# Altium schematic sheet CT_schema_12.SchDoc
size 519 x 434 mm
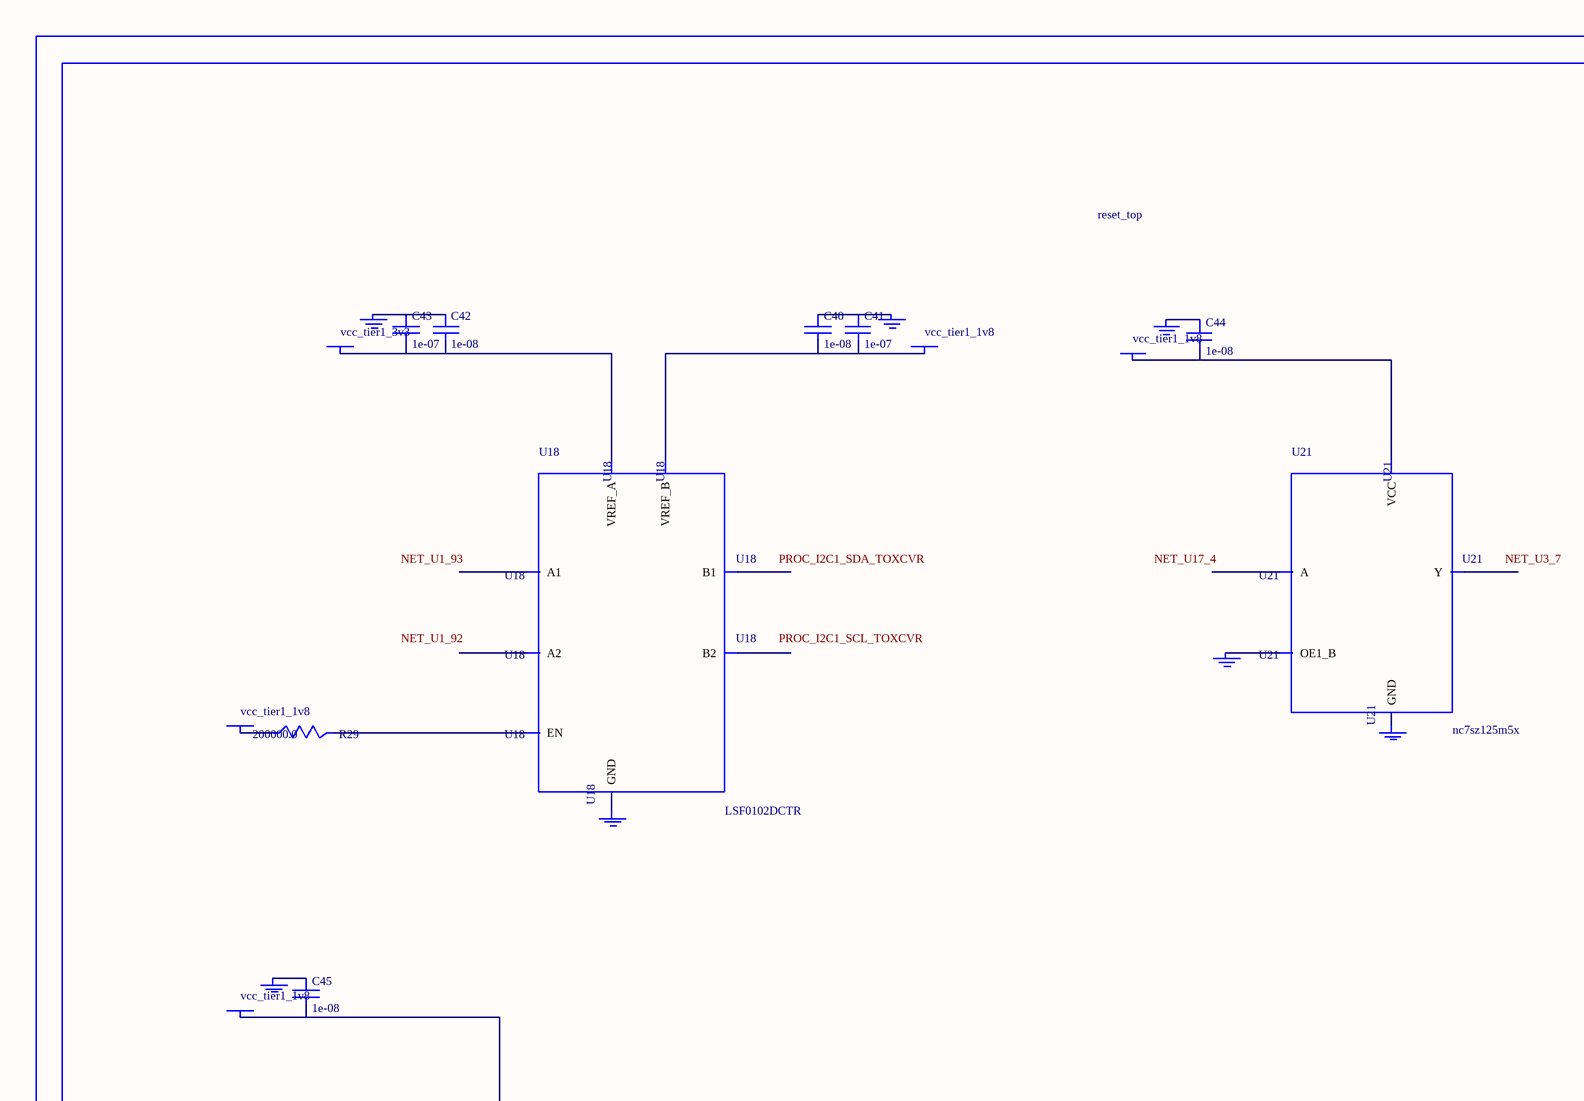
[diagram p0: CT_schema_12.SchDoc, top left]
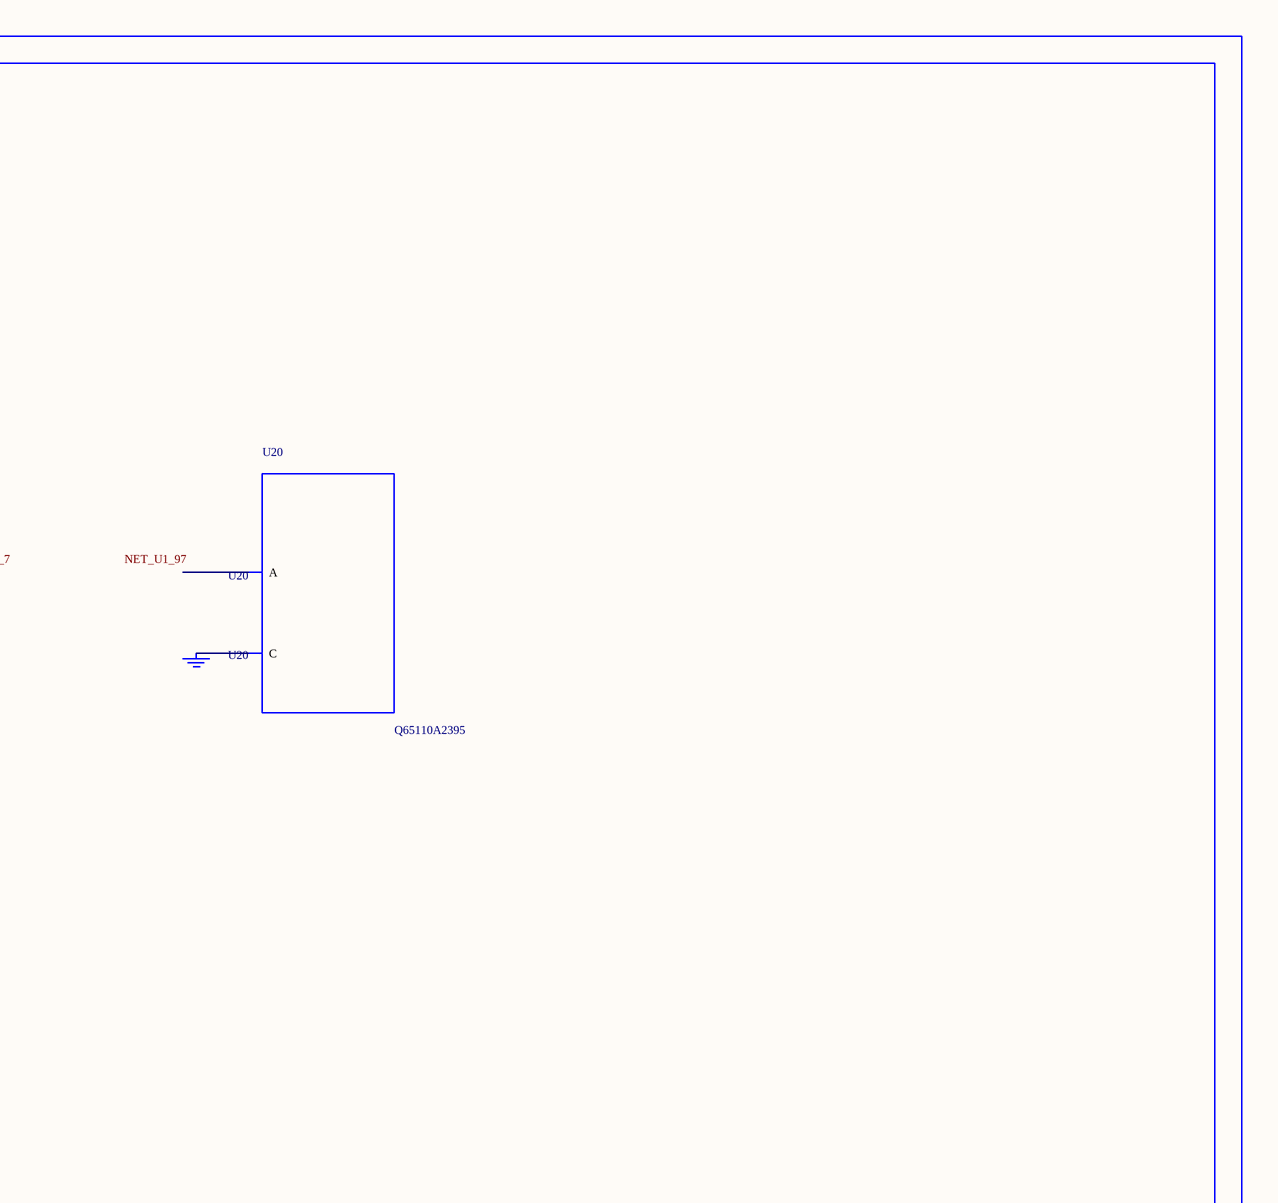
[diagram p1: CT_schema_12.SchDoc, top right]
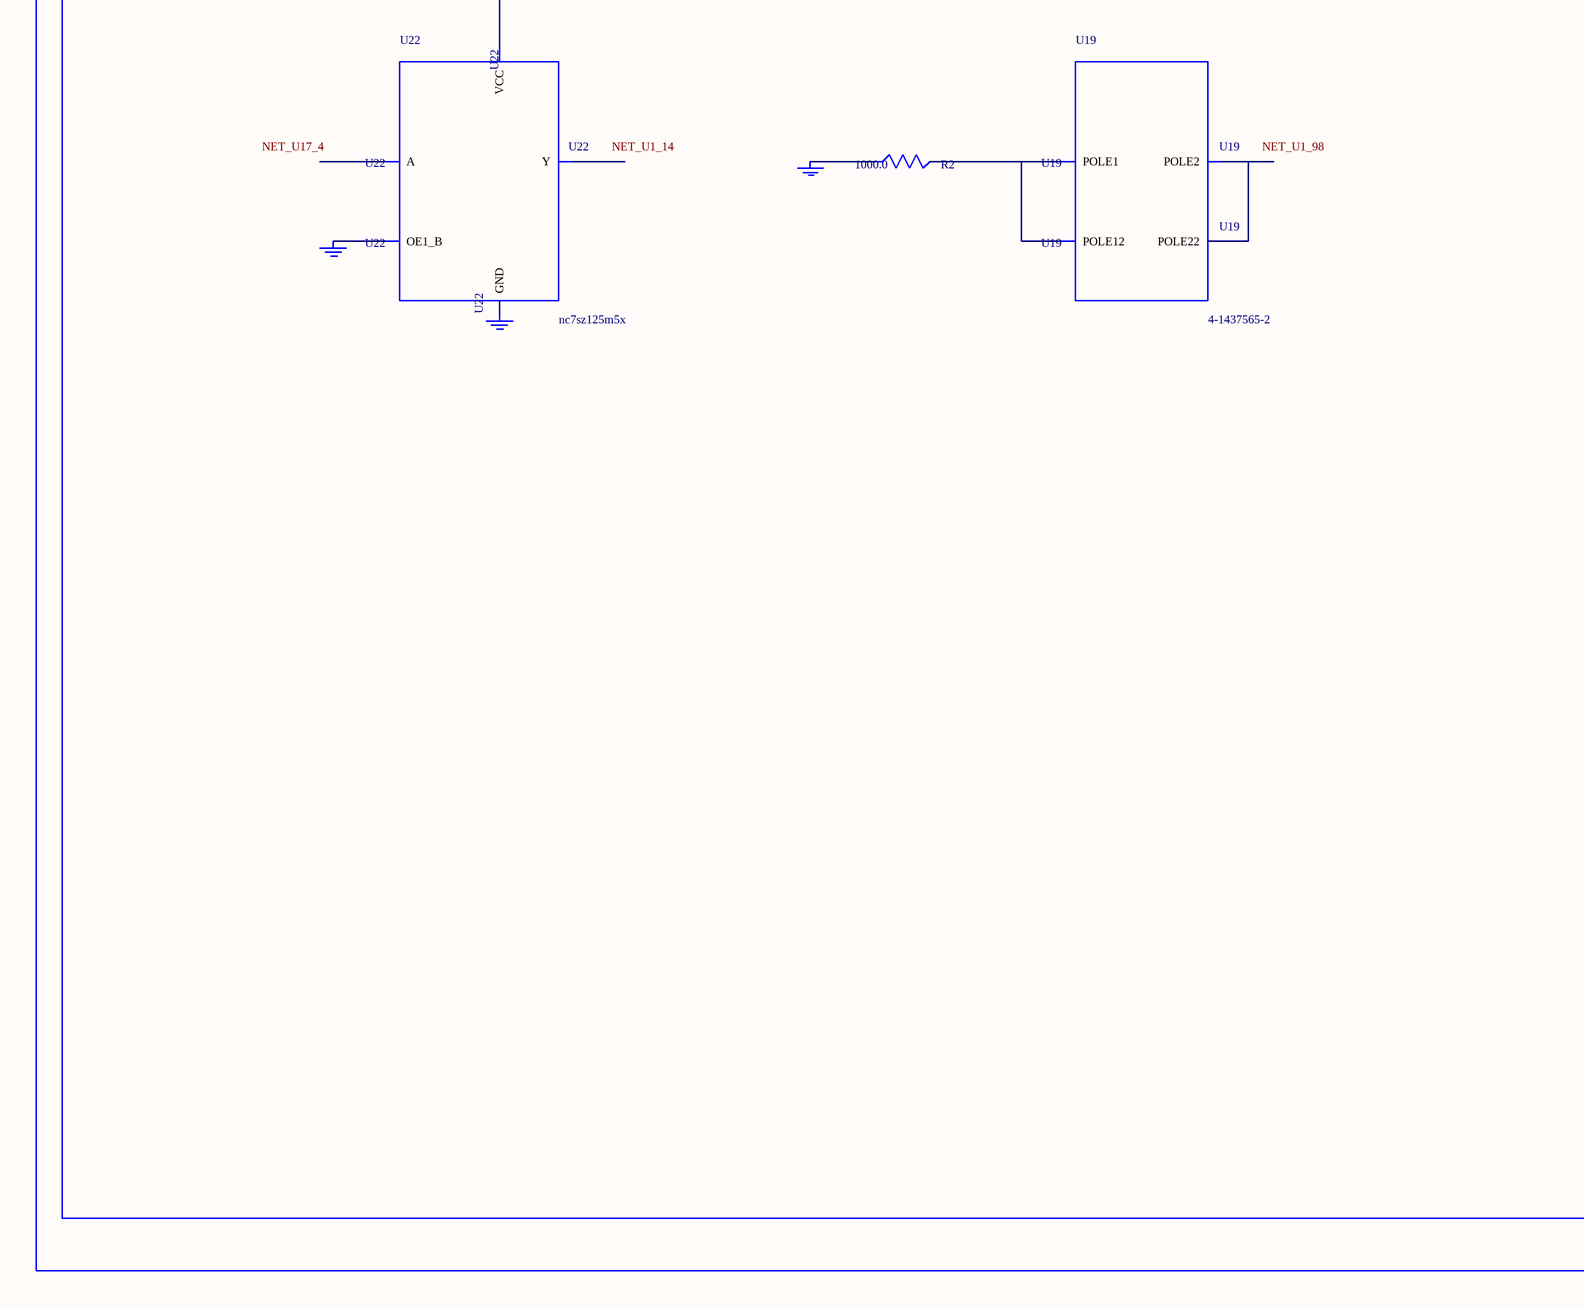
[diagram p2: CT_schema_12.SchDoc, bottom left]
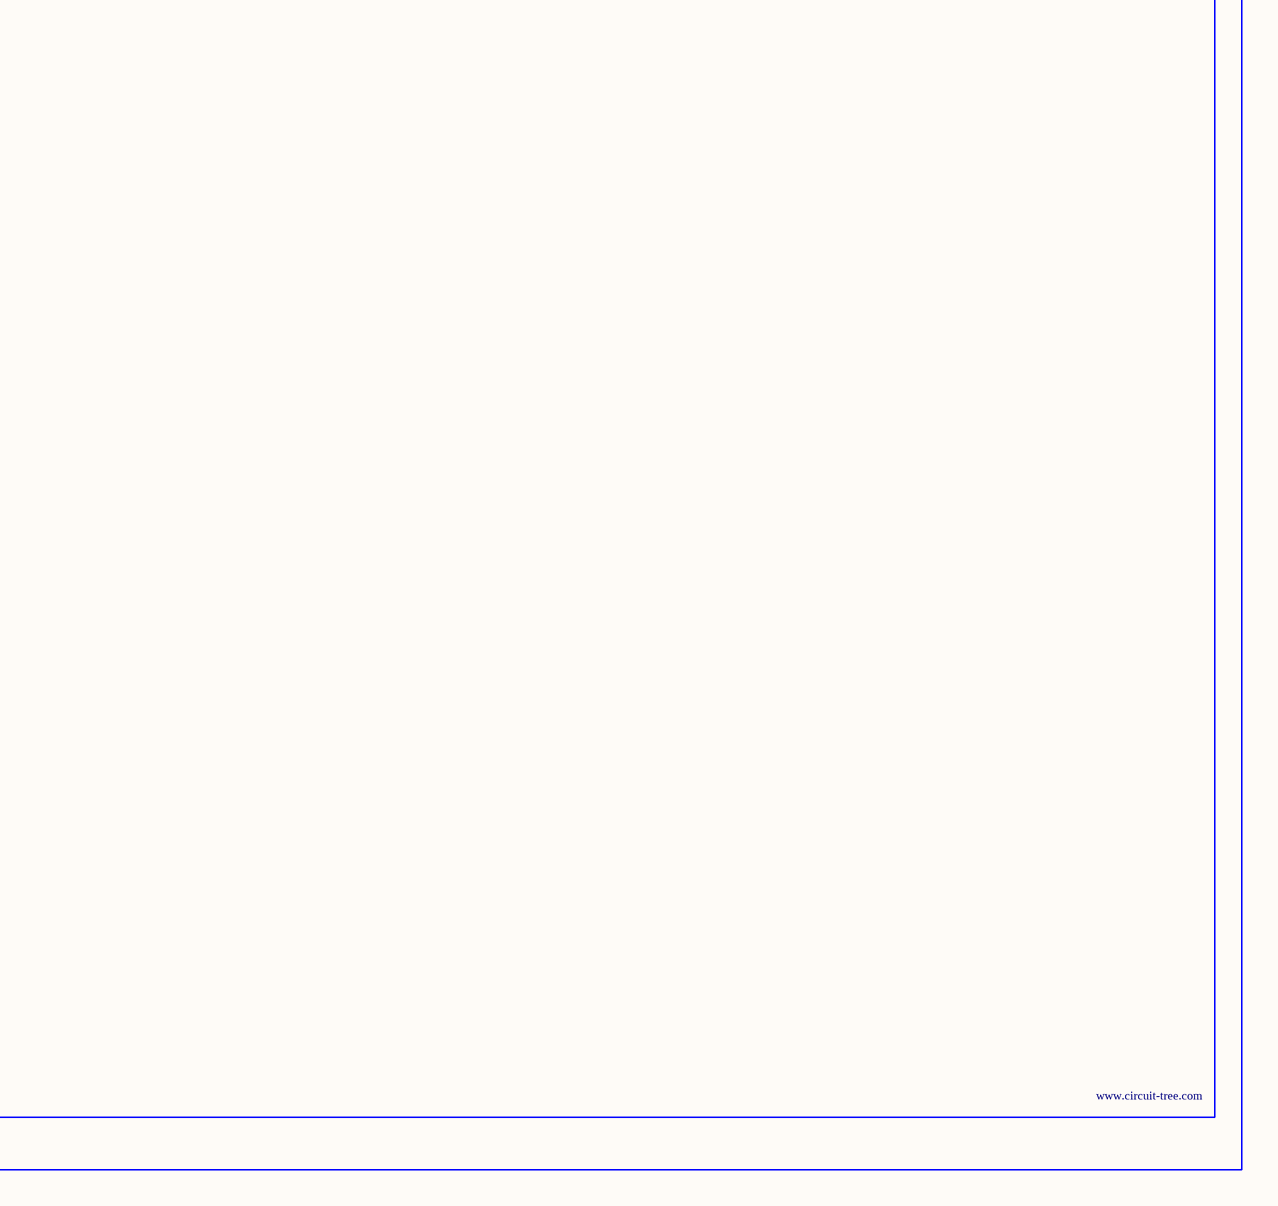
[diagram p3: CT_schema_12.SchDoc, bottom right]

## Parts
BORDER11  (no value)
C40  1e-08  [C0402]
C41  1e-07  [C0402]
C42  1e-08  [C0402]
C43  1e-07  [C0402]
C44  1e-08  [C0402]
C45  1e-08  [C0402]
GND_INSTANCE_11_0  (no value)
GND_INSTANCE_11_1  (no value)
GND_INSTANCE_11_2  (no value)
GND_INSTANCE_11_3  (no value)
GND_INSTANCE_11_4  (no value)
GND_INSTANCE_11_5  (no value)
GND_INSTANCE_11_6  (no value)
GND_INSTANCE_11_7  (no value)
GND_INSTANCE_11_8  (no value)
GND_INSTANCE_11_9  (no value)
GND_INSTANCE_11_10  (no value)
POWER_INSTANCE_11_0  vcc_tier1_3v3
POWER_INSTANCE_11_1  vcc_tier1_1v8
POWER_INSTANCE_11_2  vcc_tier1_1v8
POWER_INSTANCE_11_3  vcc_tier1_1v8
POWER_INSTANCE_11_4  vcc_tier1_1v8
R2  1000.0  [R0603]
R29  200000.0  [R0603]
U18  LSF0102DCTR  [DCU0008A_N]
U19  4-1437565-2  [SW_4-1437565-2]
U20  Q65110A2395  [LGM67K-G1J2-24-Z]
U21  nc7sz125m5x  [NC7SZ125M5X]
U22  nc7sz125m5x  [NC7SZ125M5X]

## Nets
NetC40_1: C40.1 C41.1 GND_INSTANCE_11_1.0(GND)
NetC40_2: C40.2 C41.2 POWER_INSTANCE_11_1.0(PWR) U18.7(VREF_B)
NetC42_1: C42.1 C43.1 GND_INSTANCE_11_0.0(GND)
NetC42_2: C42.2 C43.2 POWER_INSTANCE_11_0.0(PWR) U18.2(VREF_A)
NetC44_1: C44.1 GND_INSTANCE_11_5.0(GND)
NetC44_2: C44.2 POWER_INSTANCE_11_3.0(PWR) U21.5(VCC)
NetC45_1: C45.1 GND_INSTANCE_11_8.0(GND)
NetC45_2: C45.2 POWER_INSTANCE_11_4.0(PWR) U22.5(VCC)
NetGND_INSTANCE_11_2_0: GND_INSTANCE_11_2.0(GND) U18.1(GND)
NetGND_INSTANCE_11_3_0: GND_INSTANCE_11_3.0(GND) R2.1
NetGND_INSTANCE_11_4_0: GND_INSTANCE_11_4.0(GND) U20.C
NetGND_INSTANCE_11_6_0: GND_INSTANCE_11_6.0(GND) U21.1(OE1_B)
NetGND_INSTANCE_11_7_0: GND_INSTANCE_11_7.0(GND) U21.3(GND)
NetGND_INSTANCE_11_9_0: GND_INSTANCE_11_9.0(GND) U22.1(OE1_B)
NetGND_INSTANCE_11_10_0: GND_INSTANCE_11_10.0(GND) U22.3(GND)
NetPOWER_INSTANCE_11_2_0: POWER_INSTANCE_11_2.0(PWR) R29.1
NetR2_2: R2.2 U19.1(POLE1) U19.2(POLE12)
NetR29_2: R29.2 U18.8(EN)
NetU19_3: U19.3(POLE2) U19.4(POLE22)

Not connected (* = marked no-connect by the designer): U18 3(A1) 4(A2) 5(B2) 6(B1); U20 A; U21 2(A) 4(Y); U22 2(A) 4(Y)

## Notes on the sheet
- Labels drawn without touching a wire or pin: NET_U1_14, NET_U1_92, NET_U1_93, NET_U1_97, NET_U1_98, NET_U3_7, NET_U17_4, PROC_I2C1_SCL_TOXCVR, PROC_I2C1_SDA_TOXCVR

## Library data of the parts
BORDER11 = BORDER_PAGE11
C40 C42 C44 C45 = C0402C103K3RAC
C41 C43 = C0402C104K3RACTU
GND_INSTANCE_11_0-GND_INSTANCE_11_10 = GND
POWER_INSTANCE_11_0-POWER_INSTANCE_11_4 = PWR
R2 = RC0603JR-071KL
R29 = RC0603JR-07200KL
